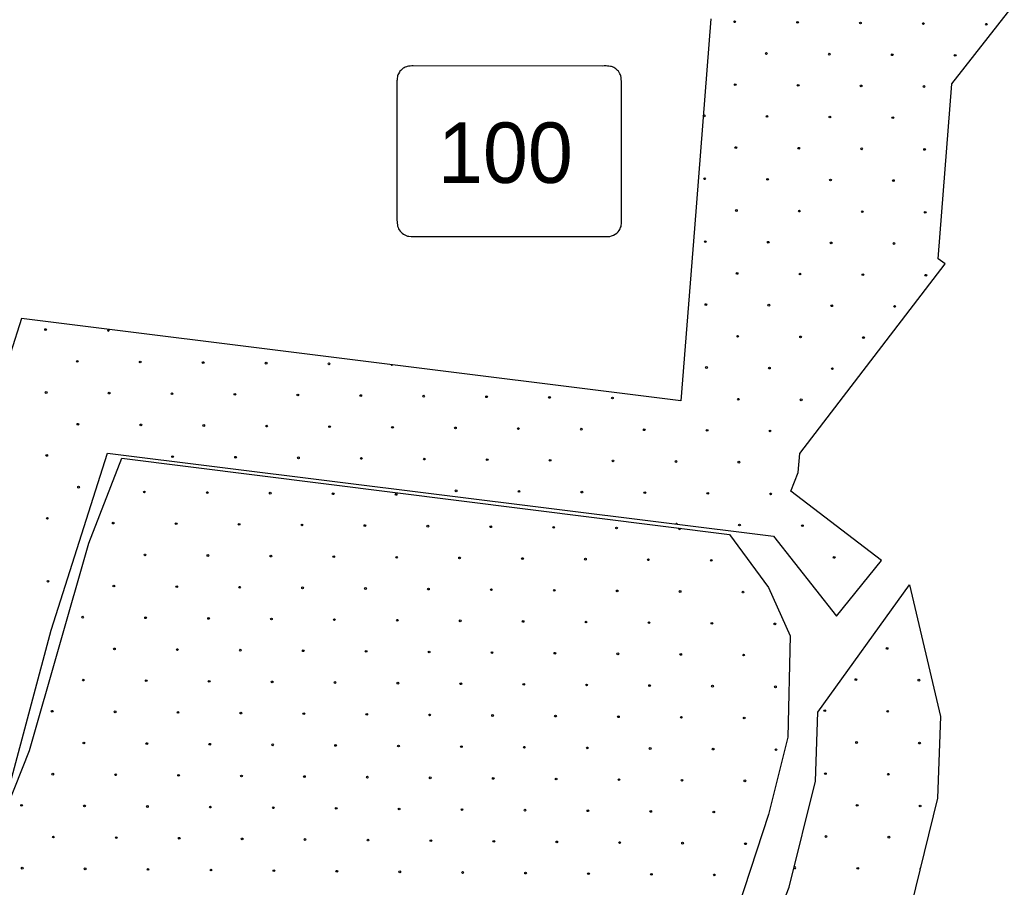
# Model space of a CAD drawing. Extents: x 1612280 to 1883141, y 560852 to 780851.
# Drawn here: x 1707678 to 1713737, y 636902 to 642204 of the extents above; entities that cross this region are included whole.
import ezdxf

# ---------------------------------------------------------------- set-up
doc = ezdxf.new("R2010")
doc.units = 0
for name, color, linetype in [('DESIGN - EROSION CONTROL - Devices', 7, 'Continuous'), ('DESIGN - ROW - Slope Lines', 7, 'Continuous'), ('DESIGN - SCRATCH - User 1', 7, 'Continuous')]:
    doc.layers.add(name, color=color, linetype=linetype)

msp = doc.modelspace()

# ---------------------------------------------------------------- linework, layer by layer
at = {"layer": 'DESIGN - EROSION CONTROL - Devices'}
for centre in [(1712046.7, 642192.4), (1712046.7, 642192.4), (1712431.2, 642188.7), (1712431.2, 642188.7), (1712815.8, 642185), (1712815.8, 642185), (1713200.3, 642181.2), (1713200.3, 642181.2), (1713584.9, 642177.5), (1713584.9, 642177.5), (1712240.8, 641998.3), (1712240.8, 641998.3), (1712625.4, 641994.5), (1712625.4, 641994.5), (1713009.9, 641990.8), (1713009.9, 641990.8), (1713394.5, 641987.1), (1713394.5, 641987.1), (1712050.4, 641807.9), (1712050.4, 641807.9), (1712435, 641804.1), (1712435, 641804.1), (1712819.5, 641800.4), (1712819.5, 641800.4), (1713204.1, 641796.7), (1713204.1, 641796.7), (1711860, 641617.5), (1711860, 641617.5), (1712244.5, 641613.7), (1712244.5, 641613.7), (1712629.1, 641610), (1712629.1, 641610), (1713013.6, 641606.3), (1713013.6, 641606.3), (1712054.1, 641423.3), (1712054.1, 641423.3), (1712438.7, 641419.6), (1712438.7, 641419.6), (1712823.2, 641415.8), (1712823.2, 641415.8), (1713207.8, 641412.1), (1713207.8, 641412.1), (1711863.7, 641232.9), (1711863.7, 641232.9), (1712248.3, 641229.2), (1712248.3, 641229.2), (1712632.8, 641225.4), (1712632.8, 641225.4), (1713017.4, 641221.7), (1713017.4, 641221.7), (1712057.9, 641038.8), (1712057.9, 641038.8), (1712442.4, 641035), (1712442.4, 641035), (1712827, 641031.3), (1712827, 641031.3), (1713211.5, 641027.6), (1713211.5, 641027.6), (1711867.5, 640848.4), (1711867.5, 640848.4), (1712252, 640844.6), (1712252, 640844.6), (1712636.6, 640840.9), (1712636.6, 640840.9), (1713021.1, 640837.2), (1713021.1, 640837.2), (1712061.6, 640654.2), (1712061.6, 640654.2), (1712446.2, 640650.5), (1712446.2, 640650.5), (1712830.7, 640646.7), (1712830.7, 640646.7), (1713215.3, 640643), (1713215.3, 640643), (1711871.2, 640463.8), (1711871.2, 640463.8), (1712255.7, 640460.1), (1712255.7, 640460.1), (1712640.3, 640456.3), (1712640.3, 640456.3), (1713024.8, 640452.6), (1713024.8, 640452.6), (1707835.3, 640310.7), (1707835.3, 640310.7), (1712065.3, 640269.7), (1712065.3, 640269.7), (1712449.9, 640265.9), (1712449.9, 640265.9), (1712834.4, 640262.2), (1712834.4, 640262.2), (1708029.4, 640116.6), (1708029.4, 640116.6), (1708413.9, 640112.8), (1708413.9, 640112.8), (1708798.5, 640109.1), (1708798.5, 640109.1), (1709183.1, 640105.4), (1709183.1, 640105.4), (1709567.6, 640101.6), (1709567.6, 640101.6), (1711874.9, 640079.2), (1711874.9, 640079.2), (1712259.5, 640075.5), (1712259.5, 640075.5), (1712644, 640071.8), (1712644, 640071.8), (1707839, 639926.2), (1707839, 639926.2), (1708223.5, 639922.4), (1708223.5, 639922.4), (1708608.1, 639918.7), (1708608.1, 639918.7), (1708992.6, 639915), (1708992.6, 639915), (1709377.2, 639911.2), (1709377.2, 639911.2), (1709761.8, 639907.5), (1709761.8, 639907.5), (1710146.3, 639903.8), (1710146.3, 639903.8), (1710530.9, 639900), (1710530.9, 639900), (1710915.4, 639896.3), (1710915.4, 639896.3), (1711300, 639892.6), (1711300, 639892.6), (1712069.1, 639885.1), (1712069.1, 639885.1), (1712453.6, 639881.4), (1712453.6, 639881.4), (1708033.1, 639732), (1708033.1, 639732), (1708417.7, 639728.3), (1708417.7, 639728.3), (1708802.2, 639724.6), (1708802.2, 639724.6), (1709186.8, 639720.8), (1709186.8, 639720.8), (1709571.3, 639717.1), (1709571.3, 639717.1), (1709955.9, 639713.4), (1709955.9, 639713.4), (1710340.4, 639709.6), (1710340.4, 639709.6), (1710725, 639705.9), (1710725, 639705.9), (1711109.6, 639702.2), (1711109.6, 639702.2), (1711494.1, 639698.4), (1711494.1, 639698.4), (1711878.7, 639694.7), (1711878.7, 639694.7), (1712263.2, 639691), (1712263.2, 639691), (1707842.7, 639541.6), (1707842.7, 639541.6), (1708611.8, 639534.2), (1708611.8, 639534.2), (1708996.4, 639530.4), (1708996.4, 639530.4), (1709380.9, 639526.7), (1709380.9, 639526.7), (1709765.5, 639523), (1709765.5, 639523), (1710150, 639519.2), (1710150, 639519.2), (1710534.6, 639515.5), (1710534.6, 639515.5), (1710919.1, 639511.8), (1710919.1, 639511.8), (1711303.7, 639508), (1711303.7, 639508), (1711688.2, 639504.3), (1711688.2, 639504.3), (1712072.8, 639500.5), (1712072.8, 639500.5), (1708036.9, 639347.5), (1708036.9, 639347.5), (1710344.2, 639325.1), (1710344.2, 639325.1), (1708439.3, 639318.2), (1708439.3, 639318.2), (1708823.9, 639314.5), (1708823.9, 639314.5), (1709208.5, 639310.8), (1709208.5, 639310.8), (1709593, 639307), (1709593, 639307), (1709977.6, 639303.3), (1709977.6, 639303.3), (1710728.7, 639321.3), (1710728.7, 639321.3), (1711113.3, 639317.6), (1711113.3, 639317.6), (1711497.8, 639313.9), (1711497.8, 639313.9), (1711882.4, 639310.1), (1711882.4, 639310.1), (1712266.9, 639306.4), (1712266.9, 639306.4), (1707846.5, 639157.1), (1707846.5, 639157.1), (1708248.9, 639127.8), (1708248.9, 639127.8), (1708633.5, 639124.1), (1708633.5, 639124.1), (1709018, 639120.4), (1709018, 639120.4), (1709402.6, 639116.6), (1709402.6, 639116.6), (1709787.1, 639112.9), (1709787.1, 639112.9), (1710171.7, 639109.2), (1710171.7, 639109.2), (1710556.3, 639105.4), (1710556.3, 639105.4), (1710940.8, 639101.7), (1710940.8, 639101.7), (1711325.4, 639098), (1711325.4, 639098), (1712076.5, 639116), (1712076.5, 639116), (1712461.1, 639112.3), (1712461.1, 639112.3), (1708443.1, 638933.7), (1708443.1, 638933.7), (1708827.6, 638929.9), (1708827.6, 638929.9), (1709212.2, 638926.2), (1709212.2, 638926.2), (1709596.7, 638922.5), (1709596.7, 638922.5), (1709981.3, 638918.7), (1709981.3, 638918.7), (1710365.8, 638915), (1710365.8, 638915), (1710750.4, 638911.3), (1710750.4, 638911.3), (1711135, 638907.5), (1711135, 638907.5), (1711519.5, 638903.8), (1711519.5, 638903.8), (1711904.1, 638900.1), (1711904.1, 638900.1), (1712655.2, 638918.1), (1712655.2, 638918.1), (1707850.2, 638772.5), (1707850.2, 638772.5), (1708252.7, 638743.3), (1708252.7, 638743.3), (1708637.2, 638739.5), (1708637.2, 638739.5), (1709021.8, 638735.8), (1709021.8, 638735.8), (1709406.3, 638732.1), (1709406.3, 638732.1), (1709790.9, 638728.3), (1709790.9, 638728.3), (1710175.4, 638724.6), (1710175.4, 638724.6), (1710560, 638720.9), (1710560, 638720.9), (1710944.5, 638717.1), (1710944.5, 638717.1), (1711329.1, 638713.4), (1711329.1, 638713.4), (1711713.6, 638709.7), (1711713.6, 638709.7), (1712098.2, 638705.9), (1712098.2, 638705.9), (1708062.3, 638552.9), (1708062.3, 638552.9), (1708446.8, 638549.1), (1708446.8, 638549.1), (1708831.4, 638545.4), (1708831.4, 638545.4), (1709215.9, 638541.7), (1709215.9, 638541.7), (1709600.5, 638537.9), (1709600.5, 638537.9), (1709985, 638534.2), (1709985, 638534.2), (1710369.6, 638530.5), (1710369.6, 638530.5), (1710754.1, 638526.7), (1710754.1, 638526.7), (1711138.7, 638523), (1711138.7, 638523), (1711523.2, 638519.3), (1711523.2, 638519.3), (1711907.8, 638515.5), (1711907.8, 638515.5), (1712292.3, 638511.8), (1712292.3, 638511.8), (1708256.4, 638358.7), (1708256.4, 638358.7), (1708641, 638355), (1708641, 638355), (1712978.6, 638361.9), (1712978.6, 638361.9), (1709025.5, 638351.2), (1709025.5, 638351.2), (1709410.1, 638347.5), (1709410.1, 638347.5), (1709794.6, 638343.8), (1709794.6, 638343.8), (1710179.2, 638340), (1710179.2, 638340), (1710563.7, 638336.3), (1710563.7, 638336.3), (1710948.3, 638332.6), (1710948.3, 638332.6), (1711332.8, 638328.8), (1711332.8, 638328.8), (1711717.4, 638325.1), (1711717.4, 638325.1), (1712101.9, 638321.4), (1712101.9, 638321.4), (1708066, 638168.3), (1708066, 638168.3), (1708450.5, 638164.6), (1708450.5, 638164.6), (1708835.1, 638160.8), (1708835.1, 638160.8), (1709219.7, 638157.1), (1709219.7, 638157.1), (1709604.2, 638153.4), (1709604.2, 638153.4), (1709988.8, 638149.6), (1709988.8, 638149.6), (1710373.3, 638145.9), (1710373.3, 638145.9), (1710757.9, 638142.2), (1710757.9, 638142.2), (1711142.4, 638138.4), (1711142.4, 638138.4), (1711527, 638134.7), (1711527, 638134.7), (1711911.5, 638131), (1711911.5, 638131), (1712296.1, 638127.2), (1712296.1, 638127.2), (1712788.2, 638171.5), (1712788.2, 638171.5), (1713172.8, 638167.7), (1713172.8, 638167.7), (1707875.6, 637977.9), (1707875.6, 637977.9), (1708260.1, 637974.2), (1708260.1, 637974.2), (1708644.7, 637970.4), (1708644.7, 637970.4), (1709029.2, 637966.7), (1709029.2, 637966.7), (1709413.8, 637963), (1709413.8, 637963), (1709798.3, 637959.2), (1709798.3, 637959.2), (1710182.9, 637955.5), (1710182.9, 637955.5), (1710567.5, 637951.8), (1710567.5, 637951.8), (1710952, 637948), (1710952, 637948), (1711336.6, 637944.3), (1711336.6, 637944.3), (1711721.1, 637940.6), (1711721.1, 637940.6), (1712105.7, 637936.8), (1712105.7, 637936.8), (1712597.8, 637981.1), (1712597.8, 637981.1), (1712982.4, 637977.3), (1712982.4, 637977.3), (1708069.7, 637783.8), (1708069.7, 637783.8), (1708454.3, 637780), (1708454.3, 637780), (1708838.8, 637776.3), (1708838.8, 637776.3), (1709223.4, 637772.6), (1709223.4, 637772.6), (1709607.9, 637768.8), (1709607.9, 637768.8), (1709992.5, 637765.1), (1709992.5, 637765.1), (1710377, 637761.4), (1710377, 637761.4), (1710761.6, 637757.6), (1710761.6, 637757.6), (1711146.2, 637753.9), (1711146.2, 637753.9), (1711530.7, 637750.2), (1711530.7, 637750.2), (1712792, 637786.9), (1712792, 637786.9), (1713176.5, 637783.2), (1713176.5, 637783.2), (1711915.3, 637746.4), (1711915.3, 637746.4), (1712299.8, 637742.7), (1712299.8, 637742.7), (1707879.3, 637593.3), (1707879.3, 637593.3), (1708263.9, 637589.6), (1708263.9, 637589.6), (1708648.4, 637585.9), (1708648.4, 637585.9), (1709033, 637582.1), (1709033, 637582.1), (1709417.5, 637578.4), (1709417.5, 637578.4), (1709802.1, 637574.7), (1709802.1, 637574.7), (1710186.6, 637570.9), (1710186.6, 637570.9), (1710571.2, 637567.2), (1710571.2, 637567.2), (1712601.6, 637596.5), (1712601.6, 637596.5), (1712986.1, 637592.8), (1712986.1, 637592.8), (1710955.7, 637563.5), (1710955.7, 637563.5), (1711340.3, 637559.7), (1711340.3, 637559.7), (1711724.8, 637556), (1711724.8, 637556), (1712109.4, 637552.3), (1712109.4, 637552.3), (1707688.9, 637402.9), (1707688.9, 637402.9), (1708073.5, 637399.2), (1708073.5, 637399.2), (1708458, 637395.5), (1708458, 637395.5), (1708842.6, 637391.7), (1708842.6, 637391.7), (1709227.1, 637388), (1709227.1, 637388), (1712795.7, 637402.4), (1712795.7, 637402.4), (1713180.2, 637398.6), (1713180.2, 637398.6), (1709611.7, 637384.3), (1709611.7, 637384.3), (1709996.2, 637380.5), (1709996.2, 637380.5), (1710380.8, 637376.8), (1710380.8, 637376.8), (1710765.3, 637373.1), (1710765.3, 637373.1), (1711149.9, 637369.3), (1711149.9, 637369.3), (1711534.4, 637365.6), (1711534.4, 637365.6), (1711919, 637361.9), (1711919, 637361.9), (1707883.1, 637208.8), (1707883.1, 637208.8), (1708267.6, 637205.1), (1708267.6, 637205.1), (1712605.3, 637212), (1712605.3, 637212), (1712989.8, 637208.2), (1712989.8, 637208.2), (1708652.2, 637201.3), (1708652.2, 637201.3), (1709036.7, 637197.6), (1709036.7, 637197.6), (1709421.3, 637193.9), (1709421.3, 637193.9), (1709805.8, 637190.1), (1709805.8, 637190.1), (1710190.4, 637186.4), (1710190.4, 637186.4), (1710574.9, 637182.7), (1710574.9, 637182.7), (1710959.5, 637178.9), (1710959.5, 637178.9), (1711344, 637175.2), (1711344, 637175.2), (1711728.6, 637171.5), (1711728.6, 637171.5), (1712113.1, 637167.7), (1712113.1, 637167.7), (1707692.6, 637018.4), (1707692.6, 637018.4), (1708077.2, 637014.6), (1708077.2, 637014.6), (1708461.7, 637010.9), (1708461.7, 637010.9), (1708846.3, 637007.2), (1708846.3, 637007.2), (1709230.9, 637003.4), (1709230.9, 637003.4), (1709615.4, 636999.7), (1709615.4, 636999.7), (1710000, 636996), (1710000, 636996), (1710384.5, 636992.2), (1710384.5, 636992.2), (1710769.1, 636988.5), (1710769.1, 636988.5), (1711153.6, 636984.8), (1711153.6, 636984.8), (1711538.2, 636981), (1711538.2, 636981), (1711922.7, 636977.3), (1711922.7, 636977.3), (1712799.4, 637017.8), (1712799.4, 637017.8)]:
    msp.add_circle(centre, 5.28, dxfattribs=at)
for centre, start, end in [((1708219.8, 640307), 116.65562, 49.11431), ((1709952.2, 640097.9), 203.84765, 321.92227), ((1711692, 639119.7), 20.16822, 145.60184), ((1711709.9, 639094.2), 137.5233, 28.15341), ((1712414.9, 637021.6), 198.68431, 133.67633), ((1713184, 637014.1), 112.07653, 220.28404)]:
    msp.add_arc(centre, 5.28, start, end, dxfattribs=at)
at = {"layer": 'DESIGN - ROW - Slope Lines'}
msp.add_line((1709982.8, 641821.1), (1709982.8, 640989.3), dxfattribs=at)
msp.add_line((1709982.8, 641821.1), (1709982.8, 640989.3), dxfattribs=at)
for points in [[(1711355.7, 641810.6), (1711355.5, 641818.4), (1711355.4, 641826.5), (1711354.3, 641841.1), (1711353, 641851.6), (1711351.2, 641862.3), (1711349.2, 641868.3), (1711346, 641874.9), (1711341.6, 641882.4), (1711336.2, 641889.8), (1711331.5, 641895.2), (1711325.6, 641900.8), (1711320.9, 641904.6), (1711314.5, 641909.1), (1711309.5, 641912.1), (1711301.1, 641916.1), (1711295, 641918.2), (1711287.9, 641919.6), (1711278.6, 641921), (1711270.5, 641921.8), (1711261.8, 641922.4), (1711249.5, 641922.5), (1711240, 641921.8), (1710082.8, 641922.5), (1710073.4, 641922.5), (1710063.1, 641921.8), (1710053.9, 641920.7), (1710044.9, 641919), (1710040.6, 641917.7), (1710033.3, 641914.6), (1710026.9, 641911.2), (1710021.7, 641908), (1710012.8, 641901.2), (1710006.7, 641895.4), (1710001.5, 641889.5), (1709997.6, 641884.2), (1709991.9, 641874.6), (1709988.5, 641867.2), (1709986.6, 641862.1), (1709985.9, 641858.3), (1709985.4, 641855), (1709984.5, 641847.7), (1709983.4, 641838.4), (1709983, 641830.5), (1709982.8, 641823.8), (1709982.8, 641805.9)], [(1711355.7, 641810.6), (1711355.5, 641818.4), (1711355.4, 641826.5), (1711354.3, 641841.1), (1711353, 641851.6), (1711351.2, 641862.3), (1711349.2, 641868.3), (1711346, 641874.9), (1711341.6, 641882.4), (1711336.2, 641889.8), (1711331.5, 641895.2), (1711325.6, 641900.8), (1711320.9, 641904.6), (1711314.5, 641909.1), (1711309.5, 641912.1), (1711301.1, 641916.1), (1711295, 641918.2), (1711287.9, 641919.6), (1711278.6, 641921), (1711270.5, 641921.8), (1711261.8, 641922.4), (1711249.5, 641922.5), (1711240, 641921.8), (1710082.8, 641922.5), (1710073.4, 641922.5), (1710063.1, 641921.8), (1710053.9, 641920.7), (1710044.9, 641919), (1710040.6, 641917.7), (1710033.3, 641914.6), (1710026.9, 641911.2), (1710021.7, 641908), (1710012.8, 641901.2), (1710006.7, 641895.4), (1710001.5, 641889.5), (1709997.6, 641884.2), (1709991.9, 641874.6), (1709988.5, 641867.2), (1709986.6, 641862.1), (1709985.9, 641858.3), (1709985.4, 641855), (1709984.5, 641847.7), (1709983.4, 641838.4), (1709983, 641830.5), (1709982.8, 641823.8), (1709982.8, 641805.9)], [(1711245.8, 640880), (1711266.4, 640880.3), (1711283.5, 640880.5), (1711293.7, 640883), (1711306, 640887.8), (1711317.1, 640894.2), (1711326.1, 640901.1), (1711334.2, 640909.1), (1711340.4, 640917), (1711346.4, 640926.8), (1711350, 640934.5), (1711352.6, 640941.6), (1711354.1, 640949.1), (1711354.9, 640957.4), (1711355.2, 640967.4), (1711355.7, 640990.7), (1711355.7, 641810.6)], [(1711245.8, 640880), (1711266.4, 640880.3), (1711283.5, 640880.5), (1711293.7, 640883), (1711306, 640887.8), (1711317.1, 640894.2), (1711326.1, 640901.1), (1711334.2, 640909.1), (1711340.4, 640917), (1711346.4, 640926.8), (1711350, 640934.5), (1711352.6, 640941.6), (1711354.1, 640949.1), (1711354.9, 640957.4), (1711355.2, 640967.4), (1711355.7, 640990.7), (1711355.7, 641810.6)], [(1709982.8, 640989.3), (1709982.9, 640980.3), (1709983.5, 640970.2), (1709984.3, 640960.7), (1709985.4, 640951.5), (1709986.8, 640942.3), (1709989.5, 640934.6), (1709993, 640927.4), (1709997.5, 640919.9), (1710002.9, 640912.6), (1710008.5, 640906.4), (1710015.7, 640899.8), (1710022.7, 640894.6), (1710030.7, 640889.9), (1710039.3, 640885.9), (1710048.2, 640882.8), (1710055.5, 640881.9), (1710070.4, 640880.7), (1710089.2, 640880), (1711245.8, 640880)], [(1709982.8, 640989.3), (1709982.9, 640980.3), (1709983.5, 640970.2), (1709984.3, 640960.7), (1709985.4, 640951.5), (1709986.8, 640942.3), (1709989.5, 640934.6), (1709993, 640927.4), (1709997.5, 640919.9), (1710002.9, 640912.6), (1710008.5, 640906.4), (1710015.7, 640899.8), (1710022.7, 640894.6), (1710030.7, 640889.9), (1710039.3, 640885.9), (1710048.2, 640882.8), (1710055.5, 640881.9), (1710070.4, 640880.7), (1710089.2, 640880), (1711245.8, 640880)]]:
    msp.add_lwpolyline(points, dxfattribs=at)
at = {"layer": 'DESIGN - SCRATCH - User 1'}
for points in [[(1713374.1, 641814), (1713736.9, 642275.7)], [(1713374.1, 641814), (1713736.9, 642275.7)], [(1711900.4, 642211), (1711800.9, 640928.5)], [(1711900.4, 642211), (1711800.9, 640928.5)], [(1713291.1, 640744.3), (1713374.1, 641814)], [(1713291.1, 640744.3), (1713374.1, 641814)], [(1711801, 640929.4), (1711717.9, 639874.8)], [(1711801, 640929.4), (1711717.9, 639874.8)], [(1713333.3, 640711.9), (1713291.1, 640744.3)], [(1713333.3, 640711.9), (1713291.1, 640744.3)], [(1712444.8, 639552.5), (1713333.3, 640711.9)], [(1712444.8, 639552.5), (1713333.3, 640711.9)], [(1707687.5, 640377.9), (1707148.5, 638683), (1706839.9, 637526.3)], [(1707687.5, 640377.9), (1707148.5, 638683), (1706839.9, 637526.3)], [(1711717.9, 639874.8), (1707687.5, 640377.9)], [(1711717.9, 639874.8), (1707687.5, 640377.9)], [(1702205.1, 631484.5), (1703518.6, 633516.1), (1704259.9, 634319.2), (1704913.5, 633760.8), (1705747.8, 634601), (1705094.2, 635186), (1705718.6, 635600.8), (1706537, 636175.2), (1707004.6, 636547.4), (1707419.1, 636941), (1707738, 637738.7), (1708099.3, 639004.4), (1708301.3, 639525.6)], [(1702205.1, 631484.5), (1703518.6, 633516.1), (1704259.9, 634319.2), (1704913.5, 633760.8), (1705747.8, 634601), (1705094.2, 635186), (1705718.6, 635600.8), (1706537, 636175.2), (1707004.6, 636547.4), (1707419.1, 636941), (1707738, 637738.7), (1708099.3, 639004.4), (1708301.3, 639525.6)], [(1707620.6, 637543.1), (1707868.6, 638472.5), (1708213.2, 639556.4)], [(1707620.6, 637543.1), (1707868.6, 638472.5), (1708213.2, 639556.4)], [(1708213.2, 639556.4), (1712284.5, 639048.2)], [(1708213.2, 639556.4), (1712284.5, 639048.2)], [(1708301.3, 639525.6), (1712016.1, 639058.8)], [(1708301.3, 639525.6), (1712016.1, 639058.8)], [(1712391, 639322.5), (1712435.8, 639437.9), (1712444.8, 639552.5)], [(1712391, 639322.5), (1712435.8, 639437.9), (1712444.8, 639552.5)], [(1712944, 638898.9), (1712391, 639322.5)], [(1712944, 638898.9), (1712391, 639322.5)], [(1712016.1, 639058.8), (1712253.9, 638734.2), (1712386.6, 638439.1), (1712371.8, 637819.3), (1712253.9, 637347.1), (1712032.7, 636668.3), (1711841, 636151.9), (1711656.7, 635842), (1711221.7, 635037.8), (1711148, 634742.7), (1710967.4, 633827.8)], [(1712016.1, 639058.8), (1712253.9, 638734.2), (1712386.6, 638439.1), (1712371.8, 637819.3), (1712253.9, 637347.1), (1712032.7, 636668.3), (1711841, 636151.9), (1711656.7, 635842), (1711221.7, 635037.8), (1711148, 634742.7), (1710967.4, 633827.8)], [(1712284.5, 639048.2), (1712669.4, 638559.5), (1712944, 638898.9)], [(1712284.5, 639048.2), (1712669.4, 638559.5), (1712944, 638898.9)], [(1712555.1, 637972.3), (1713115.2, 638751.4)], [(1712555.1, 637972.3), (1713115.2, 638751.4)], [(1713115.2, 638751.4), (1713304.6, 637945.9), (1713286.9, 637445.5), (1713097.4, 636675.2), (1713025.2, 636490.8)], [(1713115.2, 638751.4), (1713304.6, 637945.9), (1713286.9, 637445.5), (1713097.4, 636675.2), (1713025.2, 636490.8)], [(1712003.8, 636004.1), (1712182.1, 636395.1), (1712381, 636902.6), (1712540.1, 637549.4), (1712555.1, 637972.3)], [(1712003.8, 636004.1), (1712182.1, 636395.1), (1712381, 636902.6), (1712540.1, 637549.4), (1712555.1, 637972.3)]]:
    msp.add_lwpolyline(points, dxfattribs=at)

# ---------------------------------------------------------------- texts
at = {"layer": 'DESIGN - ROW - Slope Lines'}
msp.add_text('100', height=369.61, rotation=0.00107, dxfattribs=at).set_placement((1710233.6, 641207.3))
msp.add_text('100', height=369.61, rotation=0.00107, dxfattribs=at).set_placement((1710233.6, 641207.3))

doc.saveas('drawing.dxf')
